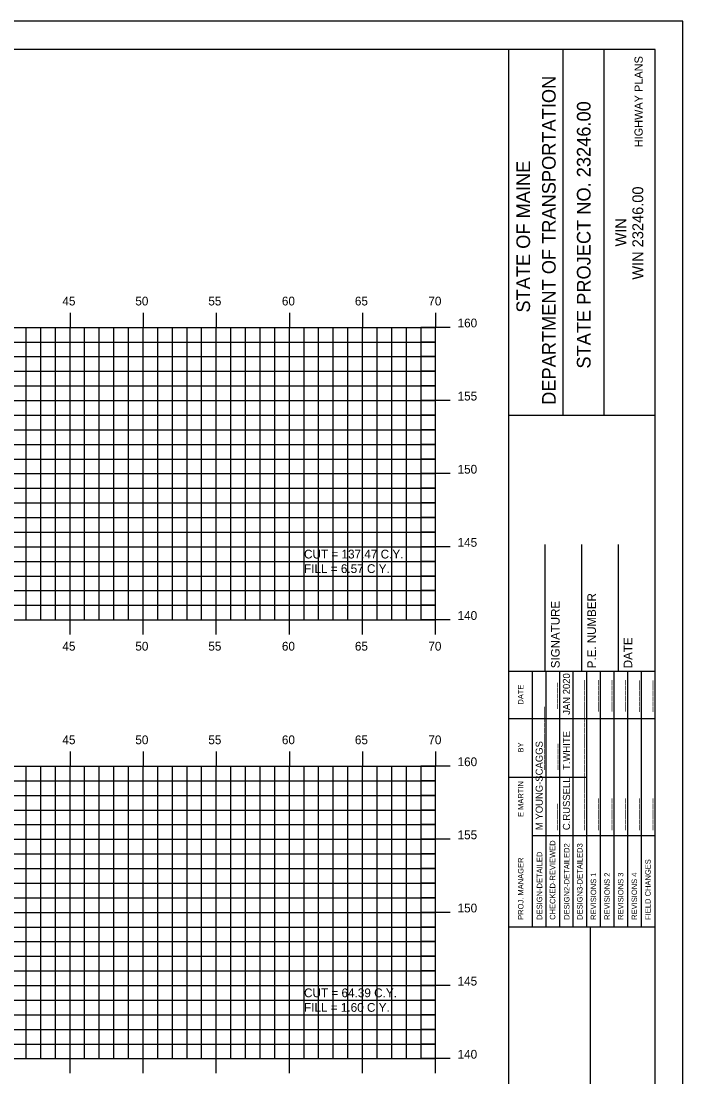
# Model space of a CAD drawing. Extents: x 1147633 to 1147803, y 608981 to 609091.
# Drawn here: x 1147758.1 to 1147803.4, y 609019.1 to 609091.3 of the extents above; entities that cross this region are included whole.
import ezdxf

# ---------------------------------------------------------------- set-up
doc = ezdxf.new("R2010")
doc.units = 0
for name, color, linetype in [('BORDER', 7, 'Continuous'), ('D_Text_Standard', 7, 'Continuous'), ('H_V ANNOTATION', 7, 'Continuous'), ('HIGHWAY_TITLE', 7, 'Continuous'), ('MAJOR', 7, 'Continuous'), ('MINOR', 7, 'Continuous'), ('PLOT BOUNDARY', 7, 'Continuous')]:
    doc.layers.add(name, color=color, linetype=linetype)

msp = doc.modelspace()

# ---------------------------------------------------------------- linework, layer by layer
at = {"layer": 'BORDER'}
for p, q in [((1147791.454, 608984.335), (1147791.454, 609089.335)), ((1147795.183, 609064.332), (1147795.183, 609089.332)), ((1147797.978, 609064.332), (1147797.978, 609089.332)), ((1147791.455, 609064.329), (1147801.454, 609064.329)), ((1147793.954, 609046.838), (1147793.954, 609055.485)), ((1147796.454, 609046.838), (1147796.454, 609055.485)), ((1147798.954, 609046.838), (1147798.954, 609055.485)), ((1147791.454, 609046.838), (1147801.454, 609046.838)), ((1147791.454, 609029.338), (1147801.454, 609029.338)), ((1147797.045, 608994.338), (1147797.045, 609029.338))]:
    msp.add_line(p, q, dxfattribs=at)
msp.add_lwpolyline([(1147641.454, 608984.335), (1147801.454, 608984.335), (1147801.454, 609089.335), (1147641.454, 609089.335)], close=True, dxfattribs=at)
for points in [[(1147793.069, 609043.588), (1147793.069, 609046.838)], [(1147794.002, 609029.341), (1147794.002, 609046.838)], [(1147794.933, 609046.838), (1147794.933, 609029.341)], [(1147795.865, 609029.341), (1147795.865, 609046.838)], [(1147796.797, 609029.341), (1147796.797, 609046.838)], [(1147797.728, 609029.341), (1147797.728, 609046.838)], [(1147798.66, 609029.341), (1147798.66, 609046.838)], [(1147799.592, 609029.341), (1147799.592, 609046.838)], [(1147800.523, 609029.341), (1147800.523, 609046.838)], [(1147793.07, 609029.341), (1147793.07, 609046.132)], [(1147791.454, 609043.588), (1147801.454, 609043.588)], [(1147791.454, 609039.588), (1147793.07, 609039.588)], [(1147793.069, 609039.588), (1147796.796, 609039.588)], [(1147793.069, 609035.588), (1147801.454, 609035.588)]]:
    msp.add_lwpolyline(points, dxfattribs=at)
at = {"layer": 'MAJOR'}
for p, q in [((1147761.454, 609071.337), (1147761.454, 609070.335)), ((1147766.454, 609071.337), (1147766.454, 609070.335)), ((1147771.454, 609071.337), (1147771.454, 609070.335)), ((1147776.454, 609071.337), (1147776.454, 609070.335)), ((1147781.454, 609071.337), (1147781.454, 609070.335)), ((1147786.454, 609071.337), (1147786.454, 609070.335)), ((1147646.454, 609070.335), (1147786.454, 609070.335)), ((1147646.454, 609070.335), (1147786.454, 609070.335)), ((1147761.454, 609050.335), (1147761.454, 609070.335)), ((1147766.454, 609050.335), (1147766.454, 609070.335)), ((1147771.454, 609050.335), (1147771.454, 609070.335)), ((1147776.454, 609050.335), (1147776.454, 609070.335)), ((1147781.454, 609050.335), (1147781.454, 609070.335)), ((1147787.456, 609070.335), (1147785.452, 609070.335)), ((1147786.454, 609050.335), (1147786.454, 609070.335)), ((1147786.454, 609050.335), (1147786.454, 609070.335)), ((1147646.454, 609065.335), (1147786.454, 609065.335)), ((1147787.456, 609065.335), (1147785.452, 609065.335)), ((1147646.454, 609060.335), (1147786.454, 609060.335)), ((1147787.456, 609060.335), (1147785.452, 609060.335)), ((1147646.454, 609055.335), (1147786.454, 609055.335)), ((1147787.456, 609055.335), (1147785.452, 609055.335)), ((1147646.454, 609050.335), (1147786.454, 609050.335)), ((1147646.454, 609050.335), (1147786.454, 609050.335)), ((1147761.454, 609049.333), (1147761.454, 609050.335)), ((1147766.454, 609049.333), (1147766.454, 609050.335)), ((1147771.454, 609049.333), (1147771.454, 609050.335)), ((1147776.454, 609049.333), (1147776.454, 609050.335)), ((1147781.454, 609049.333), (1147781.454, 609050.335)), ((1147787.456, 609050.335), (1147785.452, 609050.335)), ((1147786.454, 609049.333), (1147786.454, 609050.335)), ((1147761.454, 609041.337), (1147761.454, 609040.335)), ((1147766.454, 609041.337), (1147766.454, 609040.335)), ((1147771.454, 609041.337), (1147771.454, 609040.335)), ((1147776.454, 609041.337), (1147776.454, 609040.335)), ((1147781.454, 609041.337), (1147781.454, 609040.335)), ((1147786.454, 609041.337), (1147786.454, 609040.335)), ((1147646.454, 609040.335), (1147786.454, 609040.335)), ((1147646.454, 609040.335), (1147786.454, 609040.335)), ((1147761.454, 609020.335), (1147761.454, 609040.335)), ((1147766.454, 609020.335), (1147766.454, 609040.335)), ((1147771.454, 609020.335), (1147771.454, 609040.335)), ((1147776.454, 609020.335), (1147776.454, 609040.335)), ((1147781.454, 609020.335), (1147781.454, 609040.335)), ((1147787.456, 609040.335), (1147785.452, 609040.335)), ((1147786.454, 609020.335), (1147786.454, 609040.335)), ((1147786.454, 609020.335), (1147786.454, 609040.335)), ((1147646.454, 609035.335), (1147786.454, 609035.335)), ((1147787.456, 609035.335), (1147785.452, 609035.335)), ((1147646.454, 609030.335), (1147786.454, 609030.335)), ((1147787.456, 609030.335), (1147785.452, 609030.335)), ((1147646.454, 609025.335), (1147786.454, 609025.335)), ((1147787.456, 609025.335), (1147785.452, 609025.335)), ((1147646.454, 609020.335), (1147786.454, 609020.335)), ((1147646.454, 609020.335), (1147786.454, 609020.335)), ((1147761.454, 609019.333), (1147761.454, 609020.335)), ((1147766.454, 609019.333), (1147766.454, 609020.335)), ((1147771.454, 609019.333), (1147771.454, 609020.335)), ((1147776.454, 609019.333), (1147776.454, 609020.335)), ((1147781.454, 609019.333), (1147781.454, 609020.335)), ((1147787.456, 609020.335), (1147785.452, 609020.335)), ((1147786.454, 609019.333), (1147786.454, 609020.335))]:
    msp.add_line(p, q, dxfattribs=at)
at = {"layer": 'MINOR'}
for p, q in [((1147758.454, 609050.335), (1147758.454, 609070.335)), ((1147759.454, 609050.335), (1147759.454, 609070.335)), ((1147760.454, 609050.335), (1147760.454, 609070.335)), ((1147762.454, 609050.335), (1147762.454, 609070.335)), ((1147763.454, 609050.335), (1147763.454, 609070.335)), ((1147764.454, 609050.335), (1147764.454, 609070.335)), ((1147765.454, 609050.335), (1147765.454, 609070.335)), ((1147767.454, 609050.335), (1147767.454, 609070.335)), ((1147768.454, 609050.335), (1147768.454, 609070.335)), ((1147769.454, 609050.335), (1147769.454, 609070.335)), ((1147770.454, 609050.335), (1147770.454, 609070.335)), ((1147772.454, 609050.335), (1147772.454, 609070.335)), ((1147773.454, 609050.335), (1147773.454, 609070.335)), ((1147774.454, 609050.335), (1147774.454, 609070.335)), ((1147775.454, 609050.335), (1147775.454, 609070.335)), ((1147777.454, 609050.335), (1147777.454, 609070.335)), ((1147778.454, 609050.335), (1147778.454, 609070.335)), ((1147779.454, 609050.335), (1147779.454, 609070.335)), ((1147780.454, 609050.335), (1147780.454, 609070.335)), ((1147782.454, 609050.335), (1147782.454, 609070.335)), ((1147783.454, 609050.335), (1147783.454, 609070.335)), ((1147784.454, 609050.335), (1147784.454, 609070.335)), ((1147785.454, 609050.335), (1147785.454, 609070.335)), ((1147646.454, 609069.335), (1147786.454, 609069.335)), ((1147786.454, 609069.335), (1147785.452, 609069.335)), ((1147646.454, 609068.335), (1147786.454, 609068.335)), ((1147786.454, 609068.335), (1147785.452, 609068.335)), ((1147646.454, 609067.335), (1147786.454, 609067.335)), ((1147786.454, 609067.335), (1147785.452, 609067.335)), ((1147646.454, 609066.335), (1147786.454, 609066.335)), ((1147786.454, 609066.335), (1147785.452, 609066.335)), ((1147646.454, 609064.335), (1147786.454, 609064.335)), ((1147786.454, 609064.335), (1147785.452, 609064.335)), ((1147646.454, 609063.335), (1147786.454, 609063.335)), ((1147786.454, 609063.335), (1147785.452, 609063.335)), ((1147646.454, 609062.335), (1147786.454, 609062.335)), ((1147786.454, 609062.335), (1147785.452, 609062.335)), ((1147646.454, 609061.335), (1147786.454, 609061.335)), ((1147786.454, 609061.335), (1147785.452, 609061.335)), ((1147646.454, 609059.335), (1147786.454, 609059.335)), ((1147786.454, 609059.335), (1147785.452, 609059.335)), ((1147646.454, 609058.335), (1147786.454, 609058.335)), ((1147786.454, 609058.335), (1147785.452, 609058.335)), ((1147646.454, 609057.335), (1147786.454, 609057.335)), ((1147786.454, 609057.335), (1147785.452, 609057.335)), ((1147646.454, 609056.335), (1147786.454, 609056.335)), ((1147786.454, 609056.335), (1147785.452, 609056.335)), ((1147646.454, 609054.335), (1147786.454, 609054.335)), ((1147786.454, 609054.335), (1147785.452, 609054.335)), ((1147646.454, 609053.335), (1147786.454, 609053.335)), ((1147786.454, 609053.335), (1147785.452, 609053.335)), ((1147646.454, 609052.335), (1147786.454, 609052.335)), ((1147786.454, 609052.335), (1147785.452, 609052.335)), ((1147646.454, 609051.335), (1147786.454, 609051.335)), ((1147786.454, 609051.335), (1147785.452, 609051.335)), ((1147758.454, 609020.335), (1147758.454, 609040.335)), ((1147759.454, 609020.335), (1147759.454, 609040.335)), ((1147760.454, 609020.335), (1147760.454, 609040.335)), ((1147762.454, 609020.335), (1147762.454, 609040.335)), ((1147763.454, 609020.335), (1147763.454, 609040.335)), ((1147764.454, 609020.335), (1147764.454, 609040.335)), ((1147765.454, 609020.335), (1147765.454, 609040.335)), ((1147767.454, 609020.335), (1147767.454, 609040.335)), ((1147768.454, 609020.335), (1147768.454, 609040.335)), ((1147769.454, 609020.335), (1147769.454, 609040.335)), ((1147770.454, 609020.335), (1147770.454, 609040.335)), ((1147772.454, 609020.335), (1147772.454, 609040.335)), ((1147773.454, 609020.335), (1147773.454, 609040.335)), ((1147774.454, 609020.335), (1147774.454, 609040.335)), ((1147775.454, 609020.335), (1147775.454, 609040.335)), ((1147777.454, 609020.335), (1147777.454, 609040.335)), ((1147778.454, 609020.335), (1147778.454, 609040.335)), ((1147779.454, 609020.335), (1147779.454, 609040.335)), ((1147780.454, 609020.335), (1147780.454, 609040.335)), ((1147782.454, 609020.335), (1147782.454, 609040.335)), ((1147783.454, 609020.335), (1147783.454, 609040.335)), ((1147784.454, 609020.335), (1147784.454, 609040.335)), ((1147785.454, 609020.335), (1147785.454, 609040.335)), ((1147646.454, 609039.335), (1147786.454, 609039.335)), ((1147786.454, 609039.335), (1147785.452, 609039.335)), ((1147646.454, 609038.335), (1147786.454, 609038.335)), ((1147786.454, 609038.335), (1147785.452, 609038.335)), ((1147646.454, 609037.335), (1147786.454, 609037.335)), ((1147786.454, 609037.335), (1147785.452, 609037.335)), ((1147646.454, 609036.335), (1147786.454, 609036.335)), ((1147786.454, 609036.335), (1147785.452, 609036.335)), ((1147646.454, 609034.335), (1147786.454, 609034.335)), ((1147786.454, 609034.335), (1147785.452, 609034.335)), ((1147646.454, 609033.335), (1147786.454, 609033.335)), ((1147786.454, 609033.335), (1147785.452, 609033.335)), ((1147646.454, 609032.335), (1147786.454, 609032.335)), ((1147786.454, 609032.335), (1147785.452, 609032.335)), ((1147646.454, 609031.335), (1147786.454, 609031.335)), ((1147786.454, 609031.335), (1147785.452, 609031.335)), ((1147646.454, 609029.335), (1147786.454, 609029.335)), ((1147786.454, 609029.335), (1147785.452, 609029.335)), ((1147646.454, 609028.335), (1147786.454, 609028.335)), ((1147786.454, 609028.335), (1147785.452, 609028.335)), ((1147646.454, 609027.335), (1147786.454, 609027.335)), ((1147786.454, 609027.335), (1147785.452, 609027.335)), ((1147646.454, 609026.335), (1147786.454, 609026.335)), ((1147786.454, 609026.335), (1147785.452, 609026.335)), ((1147646.454, 609024.335), (1147786.454, 609024.335)), ((1147786.454, 609024.335), (1147785.452, 609024.335)), ((1147646.454, 609023.335), (1147786.454, 609023.335)), ((1147786.454, 609023.335), (1147785.452, 609023.335)), ((1147646.454, 609022.335), (1147786.454, 609022.335)), ((1147786.454, 609022.335), (1147785.452, 609022.335)), ((1147646.454, 609021.335), (1147786.454, 609021.335)), ((1147786.454, 609021.335), (1147785.452, 609021.335))]:
    msp.add_line(p, q, dxfattribs=at)
at = {"layer": 'PLOT BOUNDARY'}
msp.add_lwpolyline([(1147633.361, 608981.276), (1147803.361, 608981.276), (1147803.361, 609091.276), (1147633.361, 609091.276)], close=True, dxfattribs=at)

# ---------------------------------------------------------------- texts
at = {"layer": 'BORDER'}
for s, height, p in [('DEPARTMENT OF TRANSPORTATION', 0.93176, (1147794.661, 609065.041)), ('STATE PROJECT NO. 23246.00', 0.93176, (1147797.046, 609067.517)), ('STATE OF MAINE', 0.93176, (1147792.909, 609071.347)), ('WIN 23246.00', 0.74527, (1147800.65, 609073.596)), ('WIN', 0.7453, (1147799.491, 609075.865)), ('SIGNATURE', 0.5906, (1147794.935, 609047.03)), ('P.E. NUMBER', 0.59055, (1147797.415, 609047.03)), ('DATE', 0.5906, (1147799.895, 609047.03)), ('JAN 2020', 0.4845, (1147795.64, 609043.843)), ('DATE', 0.3714, (1147792.458, 609044.544)), ('_____', 0.4845, (1147794.672, 609044.243)), ('______', 0.4845, (1147796.535, 609044.063)), ('______', 0.4845, (1147797.467, 609044.065)), ('______', 0.4845, (1147798.398, 609044.067)), ('______', 0.4845, (1147799.33, 609044.067)), ('______', 0.4845, (1147800.262, 609044.036)), ('______', 0.4845, (1147801.193, 609044.036)), ('____________', 0.48455, (1147793.777, 609040.073)), ('____________', 0.48455, (1147796.535, 609040.073)), ('T.WHITE', 0.4845, (1147795.64, 609040.073)), ('BY', 0.3714, (1147792.458, 609041.273)), ('M YOUNG-SCAGGS', 0.48455, (1147793.777, 609035.961)), ('_____', 0.4845, (1147794.709, 609040.073)), ('____________', 0.48455, (1147796.535, 609035.961)), ('C.RUSSELL', 0.4845, (1147795.64, 609035.961)), ('E MARTIN', 0.3727, (1147792.458, 609036.855)), ('_____', 0.4845, (1147794.672, 609035.961)), ('______', 0.4845, (1147797.467, 609035.961)), ('______', 0.4845, (1147798.398, 609035.961)), ('______', 0.4845, (1147799.33, 609035.961)), ('______', 0.4845, (1147800.262, 609035.961)), ('______', 0.4845, (1147801.193, 609035.961)), ('CHECKED-REVIEWED', 0.37275, (1147794.635, 609029.826)), ('DESIGN2-DETAILED2', 0.37275, (1147795.604, 609029.826)), ('DESIGN3-DETAILED3', 0.37275, (1147796.499, 609029.826)), ('DESIGN-DETAILED', 0.37275, (1147793.741, 609029.826)), ('PROJ. MANAGER', 0.37275, (1147792.458, 609029.826)), ('FIELD CHANGES', 0.37275, (1147801.157, 609029.826)), ('REVISIONS 1', 0.37275, (1147797.43, 609029.826)), ('REVISIONS 2', 0.37275, (1147798.362, 609029.826)), ('REVISIONS 3', 0.37275, (1147799.294, 609029.826)), ('REVISIONS 4', 0.37275, (1147800.225, 609029.826))]:
    msp.add_text(s, height=height, rotation=90, dxfattribs=at).set_placement(p)
at = {"layer": 'D_Text_Standard'}
for s, p in [('CUT = 137.47 C.Y.', (1147777.454, 609054.535)), ('FILL = 6.57 C.Y.', (1147777.454, 609053.539)), ('CUT = 64.39 C.Y.', (1147777.454, 609024.535)), ('FILL = 1.60 C.Y.', (1147777.454, 609023.539))]:
    msp.add_text(s, height=0.6, dxfattribs=at).set_placement(p)
at = {"layer": 'H_V ANNOTATION'}
for s, p in [('45', (1147760.932, 609071.835)), ('50', (1147765.919, 609071.835)), ('55', (1147770.911, 609071.835)), ('60', (1147775.94, 609071.835)), ('65', (1147780.932, 609071.835)), ('70', (1147785.956, 609071.835)), ('160', (1147787.954, 609070.335)), ('155', (1147787.954, 609065.335)), ('150', (1147787.954, 609060.335)), ('145', (1147787.954, 609055.335)), ('140', (1147787.954, 609050.335)), ('45', (1147760.932, 609048.235)), ('50', (1147765.919, 609048.235)), ('55', (1147770.911, 609048.235)), ('60', (1147775.94, 609048.235)), ('65', (1147780.932, 609048.235)), ('70', (1147785.956, 609048.235)), ('45', (1147760.932, 609041.835)), ('50', (1147765.919, 609041.835)), ('55', (1147770.911, 609041.835)), ('60', (1147775.94, 609041.835)), ('65', (1147780.932, 609041.835)), ('70', (1147785.956, 609041.835)), ('160', (1147787.954, 609040.335)), ('155', (1147787.954, 609035.335)), ('150', (1147787.954, 609030.335)), ('145', (1147787.954, 609025.335)), ('140', (1147787.954, 609020.335))]:
    msp.add_text(s, height=0.6, dxfattribs=at).set_placement(p)
at = {"layer": 'HIGHWAY_TITLE'}
msp.add_text('HIGHWAY PLANS', height=0.55901, rotation=90, dxfattribs=at).set_placement((1147800.612, 609082.65))

doc.saveas('drawing.dxf')
